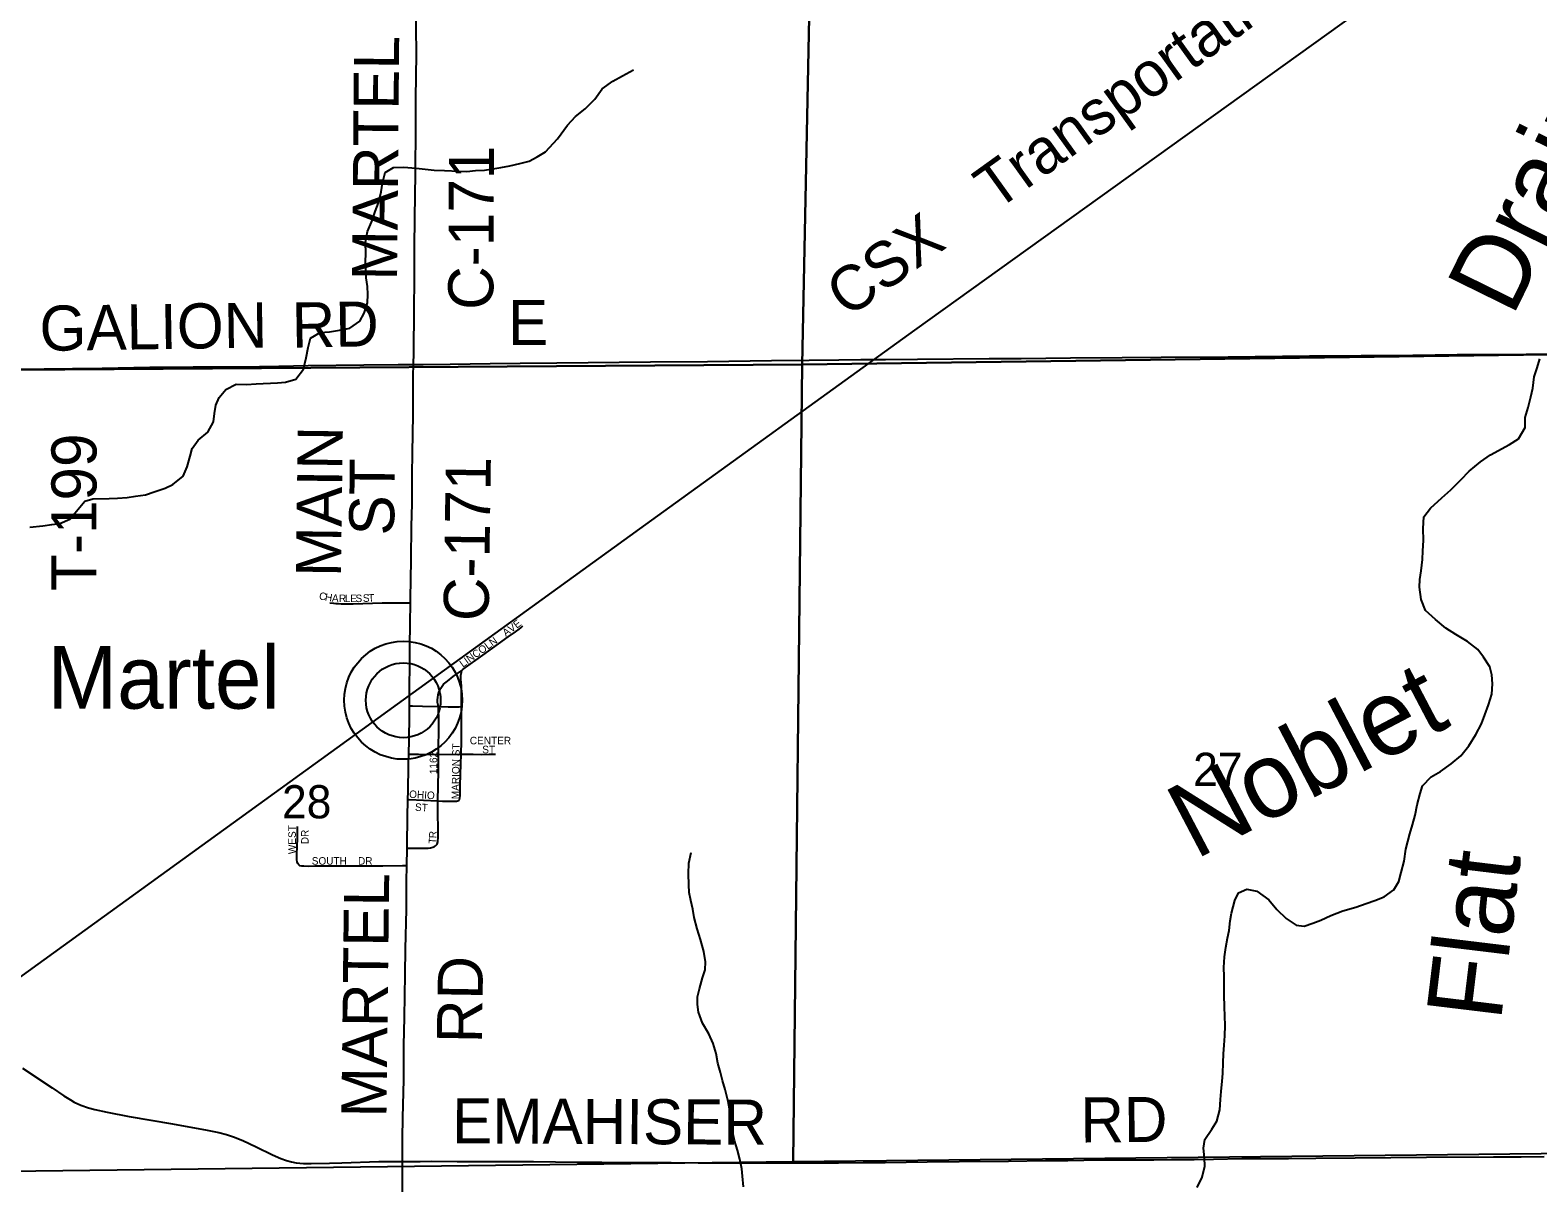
# Model space of a CAD drawing. Extents: x 1584893 to 1934202, y 663575 to 1091909.
# Drawn here: x 1852245 to 1862282, y 969268 to 976938 of the extents above; entities that cross this region are included whole.
import ezdxf

# ---------------------------------------------------------------- set-up
doc = ezdxf.new("R2010")
doc.units = 0
for name, color, linetype in [('GM_X_County_Road', 7, 'Continuous'), ('GM_X_County_Road_Text', 7, 'Continuous'), ('GM_X_Minor_River', 7, 'Continuous'), ('GM_X_Minor_River_Text', 7, 'Continuous'), ('GM_X_Rail_Line', 7, 'Continuous'), ('GM_X_Rail_Line_Text', 7, 'Continuous'), ('GM_X_Section', 7, 'Continuous'), ('GM_X_Section_Text', 7, 'Continuous'), ('GM_X_Township_Road', 7, 'Continuous'), ('GM_X_Township_Road_Text', 7, 'Continuous'), ('GM_X_Township_Subdivision', 7, 'Continuous'), ('GM_X_Township_Subdivision_Text', 7, 'Continuous'), ('GM_X_Unincorporated', 7, 'Continuous'), ('GM_X_Unincorporated_Location', 7, 'Continuous'), ('GM_X_Unincorporated_Text', 7, 'Continuous')]:
    doc.layers.add(name, color=color, linetype=linetype)

msp = doc.modelspace()

# ---------------------------------------------------------------- linework, layer by layer
at = {"layer": 'GM_X_County_Road'}
for points in [[(1854798, 974712), (1854799, 974791), (1854802, 975082), (1854804, 975281), (1854804, 975393), (1854804, 975492), (1854807, 975689), (1854810, 975984), (1854812, 976295), (1854813, 976486), (1854817, 976775), (1854816, 976957), (1854817, 977075), (1854820, 977198), (1854826, 977641), (1854829, 977874), (1854833, 978035), (1854834, 978248), (1854839, 978806), (1854840, 979085), (1854841, 979338), (1854844, 979560), (1854848, 979920), (1854850, 980044)], [(1854798, 974712), (1854862, 974714), (1855042, 974716), (1855307, 974719), (1855507, 974721), (1855752, 974724), (1856374, 974731), (1856755, 974734), (1857181, 974739), (1857432, 974742), (1857629, 974744), (1857776, 974746), (1857940, 974747), (1858153, 974749), (1858629, 974752), (1858842, 974754), (1859170, 974757), (1859515, 974759), (1859774, 974762), (1860220, 974764), (1860761, 974770), (1861106, 974773), (1861450, 974776), (1861745, 974779), (1862205, 974782), (1862533, 974787)], [(1852165, 974681), (1852339, 974685), (1852528, 974686), (1852724, 974689), (1853041, 974695), (1853330, 974698), (1853643, 974698), (1853900, 974702), (1854097, 974707), (1854466, 974710), (1854695, 974714), (1854798, 974712)], [(1854777, 973125), (1854777, 973163), (1854779, 973275), (1854781, 973420), (1854785, 973638), (1854788, 973786), (1854789, 973979), (1854791, 974125), (1854794, 974378), (1854796, 974638), (1854798, 974712)], [(1854770, 972441), (1854771, 972539), (1854772, 972739), (1854773, 972835), (1854774, 972992), (1854777, 973125)], [(1854766, 972121), (1854768, 972215), (1854770, 972378), (1854770, 972441)], [(1854760, 971819), (1854760, 971819), (1854761, 971873), (1854764, 972044), (1854766, 972121)], [(1854755, 971494), (1854755, 971494), (1854755, 971516), (1854757, 971700), (1854760, 971819)], [(1854753, 971378), (1854753, 971378), (1854755, 971494)], [(1854724, 969411), (1854724, 969411), (1854724, 969429), (1854725, 969562), (1854727, 969702), (1854732, 969954), (1854732, 970181), (1854738, 970371), (1854742, 970655), (1854745, 970825), (1854750, 971086), (1854751, 971275), (1854753, 971378)], [(1854724, 969411), (1854772, 969411), (1854842, 969411), (1854918, 969412), (1855089, 969410), (1855307, 969410), (1855456, 969409), (1855595, 969409), (1855742, 969408), (1855889, 969406), (1856050, 969405), (1856168, 969404), (1856381, 969403), (1856512, 969403), (1856693, 969402), (1856922, 969402), (1857053, 969401), (1857201, 969400), (1857299, 969400), (1857480, 969401), (1857627, 969402), (1857791, 969403), (1857938, 969404), (1858217, 969408), (1858430, 969411), (1858758, 969413), (1859004, 969416), (1859152, 969417), (1859365, 969420), (1859508, 969420), (1859725, 969422), (1859842, 969423), (1859995, 969424), (1860123, 969426), (1860311, 969429), (1860622, 969431), (1860803, 969433), (1861065, 969434), (1861540, 969438), (1861986, 969440), (1862170, 969442), (1862324, 969444)], [(1854724, 969150), (1854724, 969411)]]:
    msp.add_lwpolyline(points, dxfattribs=at)
at = {"layer": 'GM_X_Minor_River'}
for points in [[(1855505, 976051), (1855567, 976067), (1855620, 976094), (1855675, 976127), (1855756, 976214), (1855822, 976305), (1855876, 976364), (1855939, 976415), (1856004, 976479), (1856053, 976547), (1856124, 976599), (1856189, 976634), (1856262, 976673)], [(1852243, 973630), (1852330, 973640), (1852390, 973649), (1852442, 973656), (1852510, 973683), (1852564, 973750), (1852609, 973803), (1852663, 973820), (1852771, 973822), (1852827, 973824), (1852891, 973829), (1852947, 973836), (1853014, 973845), (1853070, 973866), (1853144, 973890), (1853195, 973915), (1853264, 973970), (1853291, 974031), (1853311, 974103), (1853324, 974155), (1853363, 974210), (1853428, 974263), (1853466, 974331), (1853473, 974387), (1853482, 974442), (1853503, 974494), (1853548, 974547), (1853617, 974582), (1853685, 974581), (1853749, 974585), (1853893, 974590), (1853945, 974595), (1854013, 974616), (1854065, 974683), (1854082, 974757), (1854096, 974825), (1854111, 974889), (1854176, 974925), (1854238, 974930), (1854304, 974941), (1854374, 974955), (1854441, 975002), (1854468, 975054), (1854490, 975123), (1854493, 975179), (1854490, 975232), (1854483, 975290), (1854481, 975348), (1854478, 975398), (1854479, 975450), (1854478, 975527), (1854492, 975599), (1854524, 975676), (1854541, 975730), (1854564, 975788), (1854581, 975861), (1854591, 975919), (1854608, 975991), (1854665, 976024), (1854731, 976027), (1854815, 976019), (1854875, 976012), (1854934, 976006), (1855004, 976003), (1855100, 975999), (1855152, 975998), (1855210, 976003), (1855270, 976005), (1855326, 976014), (1855379, 976023), (1855439, 976034), (1855505, 976051)], [(1860674, 970982), (1860726, 970976), (1860784, 970995), (1860837, 971016), (1860903, 971047), (1860984, 971077), (1861070, 971102), (1861139, 971126), (1861197, 971147), (1861258, 971172), (1861323, 971217), (1861356, 971272), (1861373, 971332), (1861391, 971408), (1861404, 971488), (1861416, 971540), (1861429, 971591), (1861448, 971649), (1861465, 971715), (1861479, 971783), (1861498, 971859), (1861515, 971910), (1861571, 971969), (1861633, 972006), (1861704, 972057), (1861769, 972110), (1861823, 972175), (1861870, 972252), (1861906, 972321), (1861929, 972381), (1861953, 972449), (1861976, 972520), (1861981, 972589), (1861975, 972649), (1861962, 972701), (1861921, 972766), (1861882, 972817), (1861813, 972871), (1861736, 972916), (1861669, 972958), (1861601, 973016), (1861534, 973077), (1861505, 973150), (1861495, 973232), (1861496, 973282), (1861504, 973340), (1861513, 973416), (1861516, 973473), (1861520, 973543), (1861519, 973621), (1861523, 973699), (1861568, 973756), (1861642, 973825), (1861703, 973878), (1861770, 973945), (1861825, 974004), (1861899, 974066), (1861966, 974111), (1862093, 974180), (1862154, 974219), (1862197, 974293), (1862197, 974361), (1862218, 974426), (1862236, 974498), (1862249, 974556), (1862258, 974632), (1862278, 974690), (1862295, 974750)], [(1856993, 969242), (1856988, 969312), (1856983, 969362), (1856969, 969425), (1856954, 969485), (1856935, 969550), (1856923, 969604), (1856910, 969668), (1856902, 969747), (1856891, 969809), (1856871, 969888), (1856854, 969948), (1856841, 970003), (1856824, 970065), (1856812, 970128), (1856791, 970196), (1856764, 970259), (1856720, 970330), (1856695, 970403), (1856687, 970455), (1856688, 970505), (1856701, 970559), (1856722, 970631), (1856739, 970685), (1856741, 970739), (1856730, 970807), (1856708, 970886), (1856685, 970959), (1856665, 971033), (1856656, 971088), (1856643, 971146), (1856632, 971200), (1856629, 971250), (1856627, 971325), (1856630, 971395), (1856646, 971467)], [(1860013, 969237), (1860047, 969306), (1860064, 969378), (1860062, 969434), (1860057, 969498), (1860066, 969556), (1860112, 969626), (1860145, 969679), (1860164, 969753), (1860170, 969823), (1860173, 969875), (1860180, 969945), (1860185, 969995), (1860187, 970067), (1860190, 970127), (1860193, 970183), (1860199, 970245), (1860200, 970314), (1860199, 970376), (1860197, 970438), (1860194, 970516), (1860194, 970576), (1860193, 970641), (1860192, 970701), (1860196, 970771), (1860205, 970833), (1860216, 970895), (1860226, 970947), (1860233, 971011), (1860242, 971063), (1860264, 971146), (1860289, 971198), (1860345, 971223), (1860411, 971208), (1860492, 971152), (1860544, 971086), (1860607, 971027), (1860674, 970982)]]:
    msp.add_lwpolyline(points, dxfattribs=at)
at = {"layer": 'GM_X_Rail_Line'}
for points in [[(1856303, 973619), (1858134, 974941), (1861544, 977391), (1865288, 980070), (1867429, 981609), (1869080, 982786)], [(1855926, 973347), (1856303, 973619)], [(1843186, 963859), (1847480, 967198), (1848435, 967928), (1849305, 968558), (1849800, 968917), (1855926, 973347)]]:
    msp.add_lwpolyline(points, dxfattribs=at)
at = {"layer": 'GM_X_Section'}
for points in [[(1852199, 980028), (1857493, 980105), (1857385, 974712), (1852149, 974677)], [(1857493, 980105), (1863067, 980146), (1863013, 974788), (1857385, 974712)], [(1857385, 974712), (1863013, 974788), (1862925, 969467), (1857325, 969408)], [(1852149, 974677), (1857385, 974712), (1857325, 969408), (1852104, 969344)]]:
    msp.add_lwpolyline(points, close=True, dxfattribs=at)
at = {"layer": 'GM_X_Township_Road'}
msp.add_lwpolyline([(1852195, 970031), (1852391, 969901), (1852470, 969847), (1852513, 969821), (1852538, 969805), (1852582, 969785), (1852634, 969767), (1852677, 969756), (1852759, 969739), (1852904, 969710), (1853194, 969660), (1853423, 969619), (1853502, 969603), (1853553, 969590), (1853600, 969574), (1853661, 969549), (1853750, 969507), (1853858, 969455), (1853915, 969431), (1853952, 969417), (1853985, 969407), (1854016, 969401), (1854066, 969397), (1854117, 969396), (1854238, 969398), (1854320, 969400), (1854566, 969409), (1854666, 969411), (1854724, 969411)], dxfattribs=at)
at = {"layer": 'GM_X_Township_Subdivision'}
for points in [[(1854777, 973125), (1854750, 973125), (1854686, 973126), (1854589, 973125), (1854460, 973121), (1854395, 973119), (1854330, 973119), (1854315, 973119), (1854299, 973120), (1854283, 973120), (1854268, 973122), (1854240, 973126)], [(1855118, 972678), (1855128, 972685), (1855259, 972780), (1855428, 972900), (1855477, 972934), (1855500, 972952), (1855513, 972963), (1855524, 972975)], [(1854963, 972438), (1854959, 972455), (1854958, 972465), (1854957, 972474), (1854957, 972482), (1854959, 972498), (1854962, 972514), (1854966, 972530), (1854972, 972545), (1854979, 972560), (1854988, 972573), (1854998, 972586), (1855023, 972607), (1855062, 972637), (1855118, 972678)], [(1855117, 972437), (1855117, 972464), (1855117, 972527), (1855116, 972574), (1855112, 972617), (1855112, 972645), (1855116, 972664), (1855118, 972678)], [(1854770, 972441), (1854791, 972441), (1854858, 972439), (1854963, 972438)], [(1854963, 972438), (1855027, 972436), (1855102, 972436), (1855117, 972437)], [(1854964, 972119), (1854964, 972186), (1854965, 972257), (1854965, 972314), (1854965, 972371), (1854964, 972403), (1854964, 972419), (1854963, 972436), (1854963, 972438)], [(1855114, 972120), (1855116, 972206), (1855116, 972293), (1855117, 972387), (1855117, 972437)], [(1854766, 972121), (1854799, 972120), (1854831, 972120), (1854964, 972119)], [(1854960, 971809), (1854963, 972010), (1854964, 972119)], [(1854964, 972119), (1855114, 972120)], [(1855104, 971816), (1855108, 971844), (1855109, 971878), (1855109, 971912), (1855112, 972055), (1855114, 972120)], [(1855114, 972120), (1855128, 972120), (1855194, 972120), (1855249, 972119), (1855300, 972120), (1855343, 972121)], [(1854760, 971819), (1854768, 971819), (1854960, 971809)], [(1854943, 971510), (1854949, 971515), (1854954, 971522), (1854959, 971537), (1854961, 971568), (1854961, 971612), (1854960, 971737), (1854960, 971797), (1854960, 971809)], [(1854960, 971809), (1854991, 971807), (1855084, 971807), (1855099, 971811), (1855104, 971816)], [(1854028, 971392), (1854023, 971403), (1854021, 971417), (1854021, 971450), (1854023, 971509), (1854025, 971558), (1854025, 971593), (1854025, 971640)], [(1854755, 971494), (1854780, 971494), (1854846, 971494), (1854879, 971494), (1854895, 971495), (1854911, 971497), (1854927, 971501), (1854936, 971505), (1854943, 971510)], [(1854753, 971378), (1854725, 971378), (1854593, 971375), (1854478, 971374), (1854297, 971375), (1854141, 971374), (1854097, 971373), (1854067, 971374), (1854053, 971375), (1854040, 971378), (1854033, 971384), (1854028, 971392)]]:
    msp.add_lwpolyline(points, dxfattribs=at)
at = {"layer": 'GM_X_Unincorporated'}
for radius in [393, 249]:
    msp.add_circle((1854729, 972479), radius, dxfattribs=at)
at = {"layer": 'GM_X_Unincorporated_Location'}
msp.add_line((1854729, 972479), (1854729, 972479), dxfattribs=at)

# ---------------------------------------------------------------- texts
at = {"layer": 'GM_X_County_Road_Text'}
for s, rotation, p in [('MARTEL', 89.501, (1854688, 975271)), ('C-171', 89.7259, (1855328, 975076)), ('E', 0, (1855427, 974842)), ('GALION', 0.8924, (1852310, 974803)), ('RD', 0.9813, (1853989, 974825)), ('MAIN', 89.2329, (1854314, 973298)), ('ST', 89.405, (1854668, 973574)), ('C-171', 89.1806, (1855297, 973004)), ('MARTEL', 89.3354, (1854617, 969701)), ('RD', 89.0214, (1855252, 970195)), ('EMAHISER', 359.7316, (1855054, 969531)), ('RD', 0.4874, (1859238, 969536))]:
    msp.add_text(s, height=300, rotation=rotation, dxfattribs=at).set_placement(p)
at = {"layer": 'GM_X_Minor_River_Text'}
for s, rotation, p in [('Drain', 63.8358, (1862112, 975023)), ('Noblet', 27.7101, (1860001, 971415)), ('Flat', 83.0974, (1862035, 970336))]:
    msp.add_text(s, height=500.1, rotation=rotation, dxfattribs=at).set_placement(p)
at = {"layer": 'GM_X_Rail_Line_Text'}
for s, rotation, p in [('Transportation,', 35.7108, (1858674, 975730)), ('CSX', 35.5996, (1857687, 975017))]:
    msp.add_text(s, height=299, rotation=rotation, dxfattribs=at).set_placement(p)
at = {"layer": 'GM_X_Section_Text'}
for s, p in [('27', (1859987, 971909)), ('28', (1853922, 971693))]:
    msp.add_text(s, height=221, rotation=0, dxfattribs=at).set_placement(p)
at = {"layer": 'GM_X_Township_Road_Text'}
msp.add_text('T-199', height=300, rotation=90, dxfattribs=at).set_placement((1852687, 973206))
at = {"layer": 'GM_X_Township_Subdivision_Text'}
for s, rotation, p in [('C', 350.6814, (1854166, 973150)), ('H', 350.6706, (1854205, 973143)), ('A', 355.8715, (1854253, 973135)), ('R', 359.9941, (1854301, 973132)), ('L', 0.0206, (1854340, 973132)), ('E', 0.0206, (1854376, 973132)), ('S', 0.1838, (1854411, 973132)), ('S', 2.3904, (1854461, 973133)), ('T', 2.8165, (1854497, 973134)), ('A', 36.1704, (1855412, 972901)), ('V', 36.1704, (1855448, 972927)), ('E', 37.7813, (1855485, 972954)), ('LINCOLN', 35.7537, (1855126, 972695)), ('CENTER', 0, (1855172, 972186)), ('1162', 90, (1854955, 971987)), ('MARION ST', 89.2446, (1855101, 971820)), ('ST', 0, (1855255, 972126)), ('OHIO', 356.7313, (1854767, 971830)), ('ST', 356.4254, (1854806, 971744)), ('WEST', 90, (1854014, 971455)), ('DR', 90, (1854099, 971521)), ('T', 85.3498, (1854947, 971522)), ('R', 88.0578, (1854950, 971560)), ('SOUTH', 0, (1854120, 971385)), ('DR', 0, (1854428, 971385))]:
    msp.add_text(s, height=50, rotation=rotation, dxfattribs=at).set_placement(p)
at = {"layer": 'GM_X_Unincorporated_Text'}
msp.add_text('Martel', height=417, rotation=0, dxfattribs=at).set_placement((1852360, 972423))

doc.saveas('drawing.dxf')
